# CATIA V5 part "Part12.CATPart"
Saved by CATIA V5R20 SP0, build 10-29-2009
Part number: FV161320-3
Revision: ANY
Definition: UNKNOWN
Nomenclature: FV161320-3
Source: Unknown
Bounding box of the stored display mesh (mm): x -5.25 to 5.25, y 0 to 5.8, z -5.25 to 5.25
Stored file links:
  C:\Users\Utente\Desktop\IO LAVORO\3D X SITO CF\CUMSA\3D files FV\FV 201720\Part12.CATPart
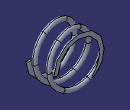
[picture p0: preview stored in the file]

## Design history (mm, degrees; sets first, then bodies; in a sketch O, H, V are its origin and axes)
Body1 "Cortar-Extruir1" (main body)
  Solid1: solid without history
